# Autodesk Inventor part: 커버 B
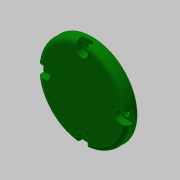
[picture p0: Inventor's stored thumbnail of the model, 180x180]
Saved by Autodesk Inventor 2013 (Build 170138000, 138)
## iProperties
Created: 2019-05
Part Number: 커버 B
Material: 알루미늄 6061
Document SubType Name: Modeling
Designer: mduedu
Density: 2.71 g/cm^3
Mass: 59.4974 g
Surface Area: 80.4581 cm^2
Volume: 21.9548 cm^3
Author: mduedu
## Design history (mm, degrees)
sketch "스케치1"
  geometry: C1 r 31 at (0, 0); 1 further point
  constraints: 1 centre point, 1 coincident
  dimensions: "d0" = 62 diameter of C1
extrude "돌출1" new body sketch "스케치1" distance "d1" = 7; taper "d2" = 0 deg
sketch "스케치3"
  geometry: C1 r 20 at (0, 0); 1 further point
  constraints: 1 centre point, 1 coincident
  dimensions: "d7" = 40 diameter of C1
extrude "돌출3" join sketch "스케치3" distance "d8" = 4; taper "d9" = 0 deg
sketch "스케치4"
  geometry: C1 r 17 at (0, 0); 1 further point
  constraints: 1 centre point, 1 coincident
  dimensions: "d10" = 34 diameter of C1
extrude "돌출4" cut sketch "스케치4" distance "d11" = 3; taper "d12" = 0 deg
fillet "모깎기3" dims "d20" = 3
fillet "모깎기4" dims "d21" = 3
chamfer "모따기1" distance "d22" = 1; stored, may be unused: second distance "d23" = 2, angle "d24" = 45 deg
sketch "스케치7" dims "d25" = 52
  geometry: L1 (-4, 26)-(-4, 30.741); L2 (4, 26)-(4, 30.741); A1 r 4 centre (0, 26) between (-4, 26) and (4, 26); A2 r 31 centre (0, 0) between (4, 30.741) and (-4, 30.741); 3 further points
  constraints: 4 end point, 4 point on circle, 2 centre point, 2 coincident, 2 tangent, 2 vertical alignment, 1 parallel, 1 vertical, 4 other
  dimensions: "d26" = 8 distance between parallel lines of L2 L1
extrude "돌출7" cut sketch "스케치7" distance "d27" = 4.4; taper "d28" = 0 deg
sketch "스케치8" dims "d36" = 52
  geometry: 6 further points
  constraints: 2 vertical alignment, 1 coincident, 7 other
  dimensions: "d39" = 360 deg dimension on point (0, 0) point (0, 26) (derived)
sketch "스케치9"
  geometry: 4 further points
  constraints: 4 other
hole "구멍1" sketch "스케치9" at (0, 52), (-26, 26), (26, 26), (0, 0) diameter "d41" = 4.5; stored, may be unused: countersink angle "d45" = 90 deg, drill point angle "d47" = 0 deg; dims "d42" = 6, "d43" = 4, "d44" = 2, "d46" = 8
node "솔리드1"
pattern_circular "원형 패턴1" dims angle "d30" = 360 deg
